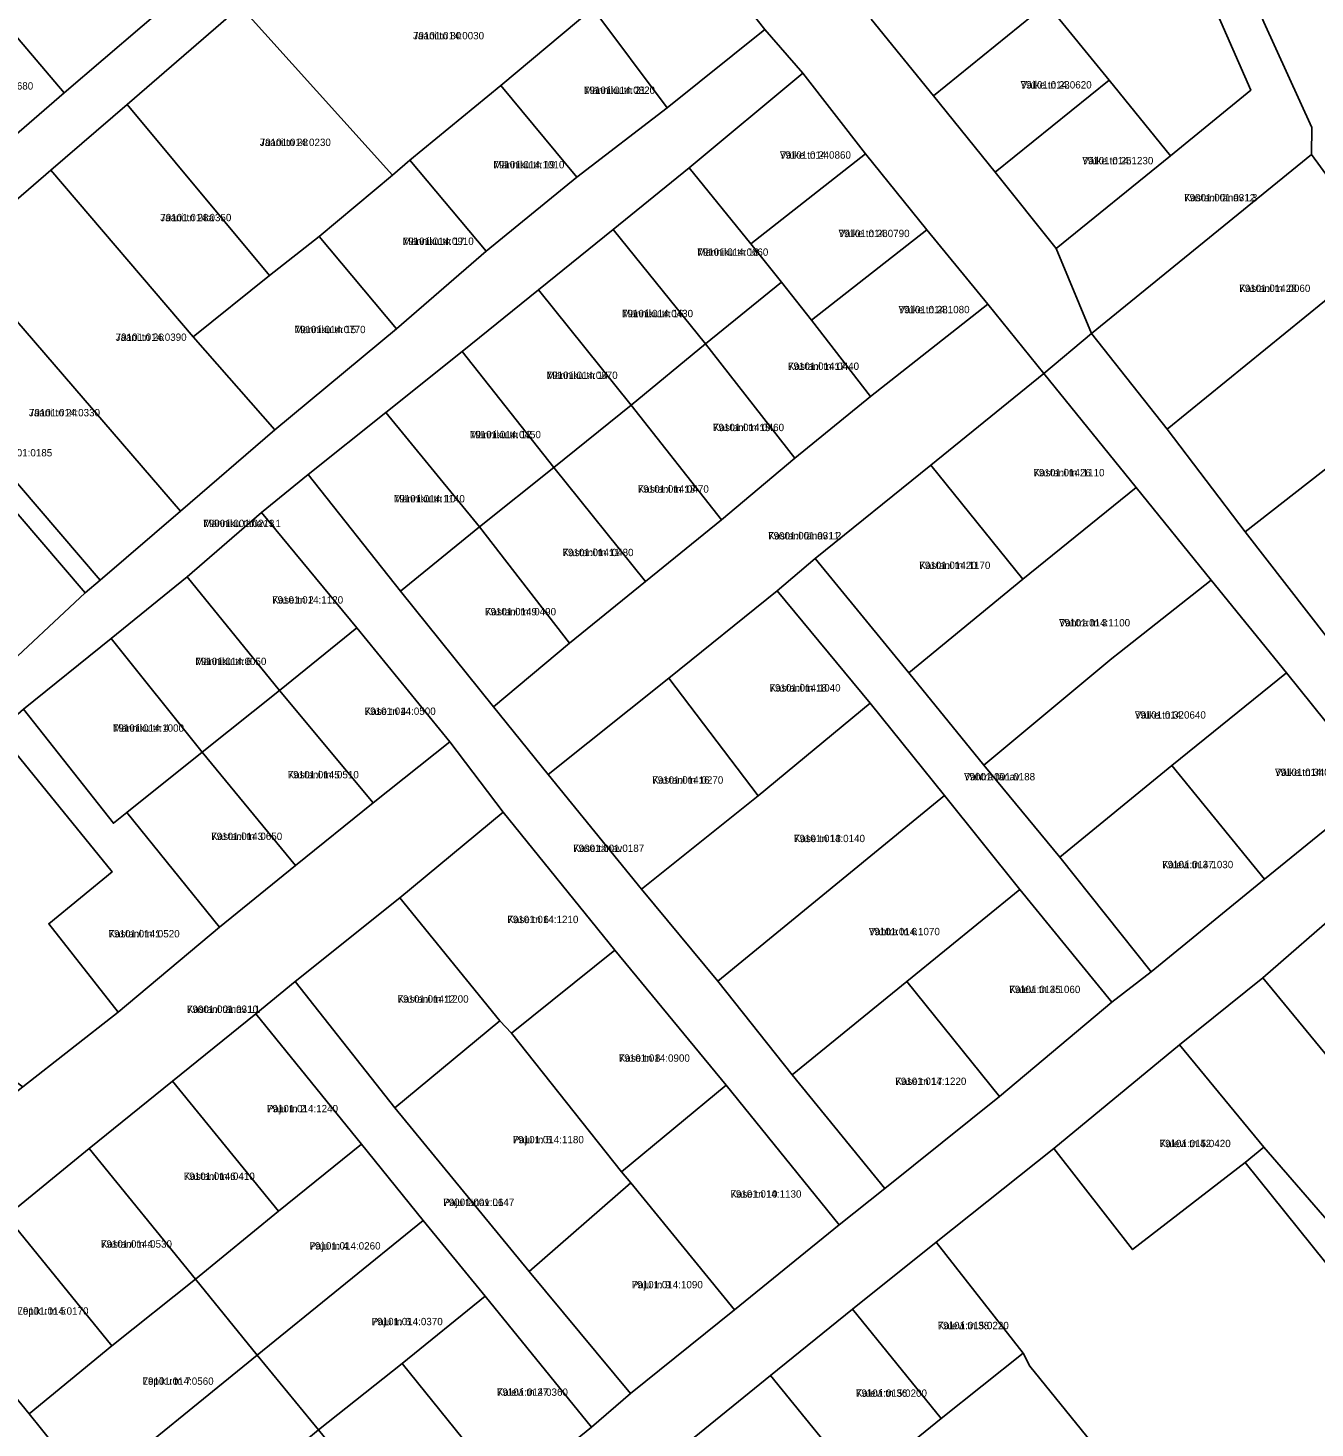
# Model space of a CAD drawing. Extents: x 587616 to 632239, y 6547421 to 6574977.
# Drawn here: x 612602.3 to 612864.9, y 6570558.1 to 6570843.8 of the extents above; entities that cross this region are included whole.
import ezdxf

# ---------------------------------------------------------------- set-up
doc = ezdxf.new("R2010")
doc.units = 0
for name, color, linetype in [('L_AADRESS', 7, 'Continuous'), ('PIIR', 7, 'Continuous'), ('TUNNUS', 7, 'Continuous')]:
    doc.layers.add(name, color=color, linetype=linetype)

msp = doc.modelspace()

# ---------------------------------------------------------------- linework, layer by layer
at = {"layer": 'PIIR'}
for points in [[(613066.18, 6570509.76), (613054.62, 6570505.86), (613043.94, 6570497.56), (613034.17, 6570509.95), (612947.74, 6570616.12), (612980.87, 6570635.47), (612962.24, 6570682.13), (612937.04, 6570717.08), (612927.83, 6570730.24), (612911.9, 6570752.2), (612895.02, 6570775.56), (612878.91, 6570797.8), (612864.22, 6570817.95), (612864.31, 6570823.48), (612854.46, 6570844.99), (612842.27, 6570873.57), (612832.9, 6570892.6), (612828.02, 6570904.09), (612863.16, 6570923.48)], [(612812.13, 6570798.78), (612835.41, 6570817.7), (612851.81, 6570831.05), (612835.45, 6570868.48), (612823.42, 6570885.08), (612832.9, 6570892.6), (612842.27, 6570873.57), (612854.46, 6570844.99), (612864.31, 6570823.48), (612864.22, 6570817.95), (612819.28, 6570781.43)], [(612609.62, 6570830.53), (612591.26, 6570852.2), (612599.5, 6570859.29), (612615.37, 6570872.59), (612633.51, 6570850.98)], [(612730.08, 6570872.01), (612752.66, 6570843.48), (612732.71, 6570827.46), (612717.54, 6570847.72), (612711.46, 6570856.93)], [(612645.61, 6570848.15), (612670.31, 6570869.17), (612686.24, 6570850.02), (612704.26, 6570865.65), (612711.46, 6570856.93), (612717.54, 6570847.72), (612698.74, 6570832.05), (612680.2, 6570816.82), (612676.67, 6570813.74)], [(612810.43, 6570848.46), (612830.73, 6570864.84), (612835.45, 6570868.48), (612851.81, 6570831.05), (612835.41, 6570817.7), (612822.94, 6570833.15)], [(612774.37, 6570845.55), (612797.68, 6570864.31), (612810.43, 6570848.46), (612809.69, 6570848.31), (612787.05, 6570829.93)], [(612567.82, 6570832.13), (612591.26, 6570852.2), (612609.62, 6570830.53), (612586.07, 6570810.2)], [(612645.61, 6570848.15), (612676.67, 6570813.74), (612661.71, 6570801.23), (612651.56, 6570793.24), (612622.48, 6570828.15)], [(612698.74, 6570832.05), (612717.54, 6570847.72), (612732.71, 6570827.46), (612714.26, 6570813.31)], [(612787.05, 6570829.93), (612809.69, 6570848.31), (612810.43, 6570848.46), (612822.94, 6570833.15), (612799.62, 6570814.38)], [(612737.19, 6570815.26), (612760.41, 6570834.52), (612773.22, 6570818.06), (612749.76, 6570799.7)], [(612799.62, 6570814.38), (612822.94, 6570833.15), (612835.41, 6570817.7), (612812.13, 6570798.78)], [(612680.2, 6570816.82), (612698.74, 6570832.05), (612714.26, 6570813.31), (612695.74, 6570798.24)], [(612622.48, 6570828.15), (612651.56, 6570793.24), (612636, 6570780.77), (612606.95, 6570814.75)], [(612661.71, 6570801.23), (612676.67, 6570813.74), (612680.2, 6570816.82), (612695.74, 6570798.24), (612677.47, 6570782.4)], [(612756.04, 6570791.93), (612749.76, 6570799.7), (612773.22, 6570818.06), (612785.69, 6570802.58), (612762.19, 6570784.14)], [(612834.74, 6570761.88), (612819.28, 6570781.43), (612864.22, 6570817.95), (612878.91, 6570797.8)], [(612606.95, 6570814.75), (612636, 6570780.77), (612652.62, 6570761.77), (612633.4, 6570745.18), (612587.65, 6570798.13)], [(612740.51, 6570779.33), (612721.66, 6570802.66), (612737.19, 6570815.26), (612749.76, 6570799.7), (612756.04, 6570791.93)], [(612636, 6570780.77), (612651.56, 6570793.24), (612661.71, 6570801.23), (612677.47, 6570782.4), (612652.62, 6570761.77)], [(612740.51, 6570779.33), (612725.34, 6570766.84), (612706.48, 6570790.33), (612721.66, 6570802.66)], [(612762.19, 6570784.14), (612785.69, 6570802.58), (612798.14, 6570787.39), (612774.23, 6570768.57)], [(612587.65, 6570798.13), (612633.4, 6570745.18), (612616.98, 6570731.13), (612571.51, 6570784.15)], [(612850.68, 6570740.97), (612834.74, 6570761.88), (612878.91, 6570797.8), (612895.02, 6570775.56)], [(612725.34, 6570766.84), (612709.59, 6570754.12), (612690.85, 6570777.76), (612706.48, 6570790.33)], [(612756.04, 6570791.93), (612762.19, 6570784.14), (612774.23, 6570768.57), (612758.77, 6570755.98), (612740.51, 6570779.33)], [(612697.23, 6570705.25), (612712.77, 6570718.21), (612728.3, 6570730.81), (612743.83, 6570743.41), (612758.77, 6570755.98), (612774.23, 6570768.57), (612798.14, 6570787.39), (612809.61, 6570773.27), (612786.53, 6570754.58), (612762.93, 6570735.54), (612755.13, 6570728.93), (612733.06, 6570711.11), (612708.41, 6570691.43)], [(612568.43, 6570781.61), (612571.51, 6570784.15), (612616.98, 6570731.13), (612613.91, 6570728.5)], [(612595.82, 6570711.62), (612549.18, 6570764.99), (612568.43, 6570781.61), (612613.91, 6570728.5)], [(612828.41, 6570749.99), (612809.61, 6570773.27), (612819.28, 6570781.43), (612834.74, 6570761.88), (612850.68, 6570740.97), (612867.71, 6570719.07), (612886.34, 6570696.13), (612895.6, 6570683.82), (612921.48, 6570650.03), (612947.74, 6570616.12), (613034.17, 6570509.95), (613043.94, 6570497.56), (613064.96, 6570469.46), (613057.06, 6570464.72), (613035.57, 6570493.51), (613027.52, 6570504.44), (612949.48, 6570601.14), (612926.11, 6570627.56), (612887.63, 6570677.6), (612877.82, 6570688.95), (612859.13, 6570712.2), (612843.71, 6570731.12)], [(612758.77, 6570755.98), (612743.83, 6570743.41), (612725.34, 6570766.84), (612740.51, 6570779.33)], [(612709.59, 6570754.12), (612694.38, 6570741.96), (612675.26, 6570765.33), (612690.85, 6570777.76)], [(612895.02, 6570775.56), (612911.9, 6570752.2), (612867.71, 6570719.07), (612850.68, 6570740.97)], [(612786.53, 6570754.58), (612809.61, 6570773.27), (612828.41, 6570749.99), (612805.33, 6570731.3)], [(612694.38, 6570741.96), (612678.29, 6570728.88), (612659.44, 6570752.67), (612675.26, 6570765.33)], [(612743.83, 6570743.41), (612728.3, 6570730.81), (612709.59, 6570754.12), (612725.34, 6570766.84)], [(612767.84, 6570599.52), (612744.76, 6570628.03), (612722.02, 6570655.61), (612699.21, 6570683.77), (612688.34, 6570698.12), (612669.4, 6570721.39), (612649.9, 6570744.88), (612659.44, 6570752.67), (612678.29, 6570728.88), (612697.23, 6570705.25), (612708.41, 6570691.43), (612727.46, 6570668.04), (612743.03, 6570649.26), (612758.22, 6570630.16), (612777.13, 6570606.98)], [(612709.59, 6570754.12), (612728.3, 6570730.81), (612712.77, 6570718.21), (612694.38, 6570741.96)], [(612805.33, 6570731.3), (612782.06, 6570712.19), (612762.93, 6570735.54), (612786.53, 6570754.58)], [(612782.06, 6570712.19), (612805.33, 6570731.3), (612828.41, 6570749.99), (612843.71, 6570731.12), (612825.04, 6570716.33), (612823.43, 6570715.14), (612797.33, 6570693.34)], [(612649.9, 6570744.88), (612669.4, 6570721.39), (612653.57, 6570708.55), (612634.76, 6570731.81)], [(612697.23, 6570705.25), (612678.29, 6570728.88), (612694.38, 6570741.96), (612712.77, 6570718.21)], [(612774.13, 6570706.01), (612755.13, 6570728.93), (612762.93, 6570735.54), (612782.06, 6570712.19), (612797.33, 6570693.34), (612812.84, 6570674.58), (612831.46, 6570651.15), (612823.44, 6570645), (612804.68, 6570667.97), (612789.33, 6570687.13)], [(612634.76, 6570731.81), (612653.57, 6570708.55), (612637.83, 6570696.01), (612619.25, 6570719.17)], [(612843.71, 6570731.12), (612859.13, 6570712.2), (612835.74, 6570693.27), (612812.84, 6570674.58), (612797.33, 6570693.34), (612823.43, 6570715.14), (612825.04, 6570716.33)], [(612733.06, 6570711.11), (612755.13, 6570728.93), (612774.13, 6570706.01), (612751.26, 6570687.11)], [(612688.34, 6570698.12), (612672.71, 6570685.64), (612653.57, 6570708.55), (612669.4, 6570721.39)], [(612601.37, 6570704.8), (612619.25, 6570719.17), (612637.83, 6570696.01), (612622.43, 6570683.68), (612619.69, 6570681.49)], [(612708.41, 6570691.43), (612733.06, 6570711.11), (612751.26, 6570687.11), (612727.46, 6570668.04)], [(612859.13, 6570712.2), (612877.82, 6570688.95), (612854.63, 6570670.1), (612835.74, 6570693.27)], [(612656.86, 6570672.87), (612637.83, 6570696.01), (612653.57, 6570708.55), (612672.71, 6570685.64)], [(612606.48, 6570660.98), (612619.43, 6570671.56), (612596.12, 6570700.23), (612601.37, 6570704.8), (612619.69, 6570681.49), (612622.43, 6570683.68), (612641.31, 6570660.3), (612620.64, 6570642.98)], [(612789.33, 6570687.13), (612743.03, 6570649.26), (612727.46, 6570668.04), (612751.26, 6570687.11), (612774.13, 6570706.01)], [(612601.19, 6570627.73), (612554.84, 6570661.14), (612561.96, 6570669.67), (612596.12, 6570700.23), (612619.43, 6570671.56), (612606.48, 6570660.98), (612620.64, 6570642.98)], [(612568.81, 6570602.35), (612601.19, 6570627.73), (612620.64, 6570642.98), (612641.31, 6570660.3), (612656.86, 6570672.87), (612672.71, 6570685.64), (612688.34, 6570698.12), (612699.21, 6570683.77), (612678.15, 6570666.25), (612656.78, 6570649.18), (612648.77, 6570642.62), (612631.73, 6570628.89), (612614.73, 6570615.16), (612597.86, 6570601.3), (612580.82, 6570587.48)], [(612656.86, 6570672.87), (612641.31, 6570660.3), (612622.43, 6570683.68), (612637.83, 6570696.01)], [(612835.74, 6570693.27), (612854.63, 6570670.1), (612831.46, 6570651.15), (612812.84, 6570674.58)], [(612639.61, 6570495.79), (612627.14, 6570511.23), (612608.16, 6570534.51), (612589.19, 6570557.93), (612570.4, 6570581.47), (612551.7, 6570604.82), (612530.58, 6570630.22), (612522.61, 6570640.4), (612505.68, 6570653.17), (612471.53, 6570678.85), (612478.97, 6570688.58), (612499.31, 6570673.44), (612528.11, 6570648.18), (612538.11, 6570640.38), (612568.81, 6570602.35), (612580.82, 6570587.48), (612602.49, 6570560.97), (612615.08, 6570545.35), (612627.71, 6570530.02), (612649.48, 6570503.22)], [(612743.03, 6570649.26), (612789.33, 6570687.13), (612804.68, 6570667.97), (612781.62, 6570649.22), (612758.22, 6570630.16)], [(612698.58, 6570641.19), (612678.15, 6570666.25), (612699.21, 6570683.77), (612722.02, 6570655.61), (612700.93, 6570638.63)], [(612804.68, 6570667.97), (612823.44, 6570645), (612800.52, 6570625.77), (612781.62, 6570649.22)], [(612656.78, 6570649.18), (612678.15, 6570666.25), (612698.58, 6570641.19), (612677.12, 6570623.45)], [(612905.44, 6570610.07), (612894.73, 6570600.77), (612854.27, 6570649.98), (612870.57, 6570664.09), (612890.72, 6570638.02), (612886.11, 6570634.63)], [(612722.02, 6570655.61), (612744.76, 6570628.03), (612723.38, 6570610.38), (612700.93, 6570638.63)], [(612837.29, 6570636.31), (612854.27, 6570649.98), (612894.73, 6570600.77), (612878.89, 6570587.24), (612854.5, 6570615.4)], [(612670.33, 6570616.04), (612648.77, 6570642.62), (612656.78, 6570649.18), (612677.12, 6570623.45), (612704.53, 6570590.04), (612725.25, 6570565.16), (612717.25, 6570558.26), (612695.57, 6570584.98), (612682.89, 6570600.42)], [(612758.22, 6570630.16), (612781.62, 6570649.22), (612800.52, 6570625.77), (612777.13, 6570606.98)], [(612648.77, 6570642.62), (612670.33, 6570616.04), (612653.36, 6570602.34), (612631.73, 6570628.89)], [(612698.58, 6570641.19), (612700.93, 6570638.63), (612723.38, 6570610.38), (612725.29, 6570608.09), (612704.53, 6570590.04), (612677.12, 6570623.45)], [(612854.5, 6570615.4), (612850.66, 6570612.27), (612827.69, 6570594.5), (612811.59, 6570615.11), (612837.29, 6570636.31)], [(612614.73, 6570615.16), (612631.73, 6570628.89), (612653.36, 6570602.34), (612636.42, 6570588.46)], [(612725.29, 6570608.09), (612723.38, 6570610.38), (612744.76, 6570628.03), (612767.84, 6570599.52), (612746.43, 6570582.22)], [(612636.42, 6570588.46), (612653.36, 6570602.34), (612670.33, 6570616.04), (612682.89, 6570600.42), (612649.04, 6570572.99)], [(612614.73, 6570615.16), (612636.42, 6570588.46), (612619.38, 6570574.83), (612597.86, 6570601.3)], [(612787.61, 6570595.99), (612811.59, 6570615.11), (612827.69, 6570594.5), (612850.66, 6570612.27), (612957.02, 6570480.03), (612910.6, 6570442.71), (612838.14, 6570531.97), (612806.71, 6570570.69), (612805.34, 6570573.35)], [(612967.79, 6570456.12), (612967.87, 6570464.53), (612957.02, 6570480.03), (612850.66, 6570612.27), (612854.5, 6570615.4), (612878.89, 6570587.24), (612978.83, 6570465.48)], [(612725.29, 6570608.09), (612746.43, 6570582.22), (612725.25, 6570565.16), (612704.53, 6570590.04)], [(612597.86, 6570601.3), (612619.38, 6570574.83), (612602.49, 6570560.97), (612580.82, 6570587.48)], [(612649.04, 6570572.99), (612682.89, 6570600.42), (612695.57, 6570584.98), (612678.64, 6570571.28), (612661.55, 6570557.72)], [(612787.61, 6570595.99), (612805.34, 6570573.35), (612788.65, 6570560.04), (612770.51, 6570582.37)], [(612602.49, 6570560.97), (612619.38, 6570574.83), (612636.42, 6570588.46), (612649.04, 6570572.99), (612615.08, 6570545.35)], [(612678.64, 6570571.28), (612695.57, 6570584.98), (612717.25, 6570558.26), (612700.23, 6570544.43)], [(612770.51, 6570582.37), (612788.65, 6570560.04), (612771.99, 6570546.5), (612753.81, 6570568.82)], [(612615.08, 6570545.35), (612649.04, 6570572.99), (612661.55, 6570557.72), (612644.56, 6570543.6), (612627.71, 6570530.02)], [(612822.79, 6570525.59), (612812.87, 6570515.47), (612800.17, 6570496.62), (612791.85, 6570492.22), (612755.24, 6570532.97), (612771.99, 6570546.5), (612788.65, 6570560.04), (612805.34, 6570573.35), (612806.71, 6570570.69), (612838.14, 6570531.97)], [(612678.64, 6570571.28), (612700.23, 6570544.43), (612683.36, 6570530.77), (612661.55, 6570557.72)], [(612753.81, 6570568.82), (612771.99, 6570546.5), (612755.24, 6570532.97), (612737.12, 6570555.28)]]:
    msp.add_lwpolyline(points, close=True, dxfattribs=at)
for points in [[(612586.07, 6570810.2), (612609.62, 6570830.53), (612633.51, 6570850.98), (612657.49, 6570871.39), (612681.48, 6570892.04), (612704.96, 6570912.48), (612706.77, 6570901.03), (612688.52, 6570885.07), (612670.31, 6570869.17), (612645.61, 6570848.15), (612622.48, 6570828.15), (612606.95, 6570814.75), (612587.65, 6570798.13)], [(612774.37, 6570845.55), (612787.05, 6570829.93), (612799.62, 6570814.38), (612812.13, 6570798.78), (612819.28, 6570781.43), (612809.61, 6570773.27), (612798.14, 6570787.39), (612785.69, 6570802.58), (612773.22, 6570818.06), (612760.41, 6570834.52), (612752.66, 6570843.48), (612730.08, 6570872.01)], [(612595.82, 6570711.62), (612613.91, 6570728.5), (612616.98, 6570731.13), (612633.4, 6570745.18), (612652.62, 6570761.77), (612677.47, 6570782.4), (612695.74, 6570798.24), (612714.26, 6570813.31), (612732.71, 6570827.46), (612752.66, 6570843.48), (612760.41, 6570834.52), (612737.19, 6570815.26), (612721.66, 6570802.66), (612706.48, 6570790.33), (612690.85, 6570777.76), (612675.26, 6570765.33), (612659.44, 6570752.67), (612649.9, 6570744.88), (612634.76, 6570731.81), (612619.25, 6570719.17), (612601.37, 6570704.8)], [(612700.23, 6570544.43), (612717.25, 6570558.26), (612725.25, 6570565.16), (612746.43, 6570582.22), (612767.84, 6570599.52), (612777.13, 6570606.98), (612800.52, 6570625.77), (612823.44, 6570645), (612831.46, 6570651.15), (612854.63, 6570670.1), (612877.82, 6570688.95), (612887.63, 6570677.6), (612870.57, 6570664.09), (612854.27, 6570649.98), (612837.29, 6570636.31), (612811.59, 6570615.11), (612787.61, 6570595.99), (612770.51, 6570582.37), (612753.81, 6570568.82), (612737.12, 6570555.28)]]:
    msp.add_lwpolyline(points, dxfattribs=at)

# ---------------------------------------------------------------- texts
at = {"layer": 'L_AADRESS'}
for s, p in [('Jaani tn 30', (612680.84, 6570841.46)), ('Väike tn 23', (612804.84, 6570831.42)), ('Männiku tn 21', (612715.73, 6570830.32)), ('Jaani tn 28', (612649.57, 6570819.69)), ('Väike tn 24', (612755.71, 6570817.11)), ('Männiku tn 19', (612697.23, 6570815.13)), ('Väike tn 25', (612817.43, 6570815.96)), ('Kastani tänav L3', (612838.22, 6570808.4)), ('Jaani tn 28a', (612629.26, 6570804.34)), ('Väike tn 26', (612767.68, 6570801.1)), ('Männiku tn 17', (612678.73, 6570799.51)), ('Männiku tn 18', (612738.85, 6570797.29)), ('Kastani tn 28', (612849.47, 6570789.91)), ('Väike tn 28', (612779.93, 6570785.57)), ('Männiku tn 16', (612723.49, 6570784.76)), ('Jaani tn 26', (612620.13, 6570779.93)), ('Männiku tn 15', (612656.65, 6570781.5)), ('Kastani tn 17', (612757.37, 6570774.01)), ('Männiku tn 14', (612708.1, 6570772.16)), ('Jaani tn 24', (612602.45, 6570764.53)), ('Männiku tn 12', (612692.43, 6570760.06)), ('Kastani tn 15', (612742.06, 6570761.51)), ('Kastani tn 26', (612807.47, 6570752.29)), ('Kastani tn 13', (612726.71, 6570748.95)), ('Männiku tn 10', (612676.91, 6570746.97)), ('Männiku tänav L1', (612638.04, 6570741.93)), ('Kastani tänav L2', (612753.31, 6570739.41)), ('Kastani tn 11', (612711.34, 6570736)), ('Kastani tn 20', (612784.17, 6570733.38)), ('Kase tn 2', (612652.08, 6570726.32)), ('Kastani tn 9', (612695.53, 6570723.92)), ('Vahtra tn 3', (612812.69, 6570721.66)), ('Männiku tn 6', (612636.41, 6570713.77)), ('Kastani tn 18', (612753.6, 6570708.37)), ('Kase tn 4', (612670.96, 6570703.61)), ('Väike tn 32', (612828.15, 6570702.85)), ('Männiku tn 4', (612619.6, 6570700.17)), ('Väike tn 34', (612856.76, 6570691.15)), ('Kastani tn 5', (612655.27, 6570690.66)), ('Kastani tn 16', (612729.66, 6570689.57)), ('Vahtra tänav', (612793.3, 6570690.25)), ('Kastani tn 3', (612639.64, 6570678.08)), ('Kase tn 13', (612758.58, 6570677.64)), ('Kase tänav', (612713.52, 6570675.64)), ('Kalevi tn 37', (612833.74, 6570672.32)), ('Kase tn 6', (612700.09, 6570661.12)), ('Kastani tn 1', (612618.71, 6570658.2)), ('Vahtra tn 6', (612773.86, 6570658.65)), ('Kalevi tn 35', (612802.53, 6570646.84)), ('Kastani tänav L1', (612634.7, 6570642.8)), ('Kastani tn 12', (612677.68, 6570644.89)), ('Kase tn 8', (612722.84, 6570632.83)), ('Kase tn 17', (612779.27, 6570628.1)), ('Paju tn 2', (612651.03, 6570622.52)), ('Paju tn 5', (612701.2, 6570616.19)), ('Kalevi tn 42', (612833.22, 6570615.4)), ('Kastani tn 6', (612634.04, 6570608.72)), ('Paju tänav L1', (612687.01, 6570603.4)), ('Kase tn 10', (612745.61, 6570605.1)), ('Kastani tn 4', (612617.14, 6570594.89)), ('Paju tn 4', (612659.71, 6570594.51)), ('Paju tn 9', (612725.48, 6570586.6)), ('Lepiku tn 5', (612600.1, 6570581.22)), ('Paju tn 6', (612672.4, 6570579.07)), ('Kalevi tn 38', (612787.93, 6570578.26)), ('Lepiku tn 7', (612625.64, 6570566.91)), ('Kalevi tn 27', (612697.95, 6570564.66)), ('Kalevi tn 36', (612771.23, 6570564.46))]:
    msp.add_text(s, height=1.5, dxfattribs=at).set_placement(p)
at = {"layer": 'TUNNUS'}
for s, p in [('79101:014:0030', (612680.84, 6570841.46)), ('79101:012:0680', (612588.82, 6570831.2)), ('79101:014:0620', (612804.84, 6570831.42)), ('79101:014:0820', (612715.73, 6570830.32)), ('79101:014:0230', (612649.57, 6570819.69)), ('79101:014:0860', (612755.71, 6570817.11)), ('79101:014:1010', (612697.23, 6570815.13)), ('79101:014:1230', (612817.43, 6570815.96)), ('79001:001:0312', (612838.22, 6570808.4)), ('79101:014:0350', (612629.26, 6570804.34)), ('79101:014:0790', (612767.68, 6570801.1)), ('79101:014:0910', (612678.73, 6570799.51)), ('79101:014:0660', (612738.85, 6570797.29)), ('79101:014:0060', (612849.47, 6570789.91)), ('79101:014:1080', (612779.93, 6570785.57)), ('79101:014:0430', (612723.49, 6570784.76)), ('79101:014:0390', (612620.13, 6570779.93)), ('79101:014:0770', (612656.65, 6570781.5)), ('79101:014:0440', (612757.37, 6570774.01)), ('79101:014:0870', (612708.1, 6570772.16)), ('79101:014:0330', (612602.45, 6570764.53)), ('79101:014:0450', (612692.43, 6570760.06)), ('79101:014:0460', (612742.06, 6570761.51)), ('79001:001:0185', (612592.7, 6570756.35)), ('79101:014:1110', (612807.47, 6570752.29)), ('79101:014:0470', (612726.71, 6570748.95)), ('79101:014:1140', (612676.91, 6570746.97)), ('79001:001:0213', (612638.04, 6570741.93)), ('79001:001:0311', (612753.31, 6570739.41)), ('79101:014:0480', (612711.34, 6570736)), ('79101:014:1170', (612784.17, 6570733.38)), ('79101:014:1120', (612652.08, 6570726.32)), ('79101:014:0490', (612695.53, 6570723.92)), ('79101:014:1100', (612812.69, 6570721.66)), ('79101:014:0050', (612636.41, 6570713.77)), ('79101:014:1040', (612753.6, 6570708.37)), ('79101:014:0500', (612670.96, 6570703.61)), ('79101:014:0640', (612828.15, 6570702.85)), ('79101:014:1000', (612619.6, 6570700.17)), ('79101:014:0006', (612856.76, 6570691.15)), ('79101:014:0510', (612655.27, 6570690.66)), ('79101:014:0270', (612729.66, 6570689.57)), ('79001:001:0188', (612793.3, 6570690.25)), ('79101:014:0650', (612639.64, 6570678.08)), ('79101:014:0140', (612758.58, 6570677.64)), ('79001:001:0187', (612713.52, 6570675.64)), ('79101:014:1030', (612833.74, 6570672.32)), ('79101:014:1210', (612700.09, 6570661.12)), ('79101:014:0520', (612618.71, 6570658.2)), ('79101:014:1070', (612773.86, 6570658.65)), ('79101:014:1060', (612802.53, 6570646.84)), ('79001:001:0310', (612634.7, 6570642.8)), ('79101:014:1200', (612677.68, 6570644.89)), ('79101:014:0900', (612722.84, 6570632.83)), ('79101:014:1220', (612779.27, 6570628.1)), ('79101:014:1240', (612651.03, 6570622.52)), ('79101:014:1180', (612701.2, 6570616.19)), ('79101:015:0420', (612833.22, 6570615.4)), ('79101:014:0410', (612634.04, 6570608.72)), ('79001:001:0647', (612687.01, 6570603.4)), ('79101:014:1130', (612745.61, 6570605.1)), ('79101:014:0530', (612617.14, 6570594.89)), ('79101:014:0260', (612659.71, 6570594.51)), ('79101:014:1090', (612725.48, 6570586.6)), ('79101:014:0170', (612600.1, 6570581.22)), ('79101:014:0370', (612672.4, 6570579.07)), ('79101:015:0220', (612787.93, 6570578.26)), ('79101:014:0560', (612625.64, 6570566.91)), ('79101:014:0360', (612697.95, 6570564.66)), ('79101:015:0200', (612771.23, 6570564.46))]:
    msp.add_text(s, height=1.5, dxfattribs=at).set_placement(p)

doc.saveas('drawing.dxf')
